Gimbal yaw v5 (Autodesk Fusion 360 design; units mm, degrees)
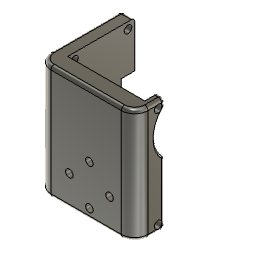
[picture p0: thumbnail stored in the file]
sketch "草图1" plane through (0, 0, 0) normal (1, 0, 0) x axis (0, 1, 0)
  line L1 (-10, 3.25) -> (-6, 3.25)
  line L2 (10, -1.75) -> (-10, -1.75)
  line L3 (10, 3.25) -> (6, 3.25)
  line L4 (-10, -17) -> (10, -17)
  line L5 (10, 17) -> (-10, 17)
  line L6 (10, 17) -> (-10, -17)
  line L7 (10, -6.75) -> (10, 3.25)
  line L8 (10, -17) -> (10, 17)
  line L9 (-10, 3.25) -> (-6, -6.75)
  line L10 (-6, 3.25) -> (-10, -6.75)
  line L11 (6, -6.75) -> (10, -6.75)
  line L12 (-10, -6.75) -> (-10, 3.25)
  line L13 (-6, 3.25) -> (-6, -6.75)
  line L14 (6, 3.25) -> (6, -6.75)
  line L15 (10, 0) -> (-10, 0)
  line L16 (-6, -6.75) -> (-10, -6.75)
  line L17 (0, -17) -> (0, 17)
  line L18 (-10, 17) -> (-10, -17)
  line L19 (-10, 17) -> (10, -17)
  circle C1 centre (0, 8) radius 1.3
  circle C2 centre (0, 8) radius 3
  circle C3 centre (8, -15) radius 1.125
  circle C4 centre (0, 8) radius 4
  circle C5 centre (-8, 15) radius 1.125
  circle C6 centre (8, 15) radius 1.125
  circle C7 centre (-8, -15) radius 1.125
  circle C8 centre (0, 8) radius 9
  point P26 (0, 0)
  point P21 (0, 0)
  point P8 (-8, -1.75)
  point P4 (-10, -6.75)
  point P19 (0, 17)
  point P20 (0, -17)
  point P10 (10, -6.75)
  point P5 (-6, -6.75)
  point P12 (6, -6.75)
  point P6 (-6, 3.25)
  point P11 (6, 3.25)
  point P7 (-10, 3.25)
  point P9 (10, 3.25)
  point P3 (10, -1.75)
  point P2 (-10, -1.75)
  point P13 (0, 8)
  point P15 (-10, 0)
  point P29 (10, 0)
  point P1 (0, 0)
  point P24 (-10, 17)
  point P25 (10, 17)
  point P22 (10, -17)
  point P14 (-8, 15)
  horizontal L4
  perpendicular L4 L18
  parallel L4 L5
  parallel L8 L18
  coincident P26 L19
  coincident P26 L6
  coincident P21 P26
  horizontal L16
  perpendicular L13 L16
  parallel L1 L16
  parallel L12 L13
  coincident P8 L10
  coincident P8 L9
  coincident P4 L18
  coincident P8 L2
  midpoint P19 L5
  midpoint P20 L4
  symmetric P4 P10 L17
  symmetric P5 P12 L17
  symmetric P6 P11 L17
  symmetric P7 P9 L17
  midpoint P3 L7
  midpoint P2 L12
  coincident P13 L17
  midpoint P15 L18
  midpoint P29 L8
  symmetric C5 C6 L17
  symmetric C5 C7 L15
  symmetric C3 C6 L15
  concentric C1 C2
  concentric C2 C4
  coincident P1 P26
  concentric C1 C8
  dimension "d1" distance P24 P25 = 20
  dimension "d2" distance P22 P25 = 34
  dimension "d3" distance P5 P6 = 10
  dimension "d4" distance P6 P7 = 4
  dimension "d5" diameter C1 = 2.6
  dimension "d6" distance P14 L17 = 8
  dimension "d7" distance P14 L15 = 15
  dimension "d8" diameter C5 = 2.25
  dimension "d9" distance P13 P14 = 7
  dimension "d10" diameter C2 = 6
  dimension "d11" diameter C4 = 8
  dimension "d12" distance L4 L11 = 10.25
  dimension "d81" diameter C8 = 18
sketch "草图2" plane through (0, 0, 0) normal (1, 0, 0) x axis (0, 1, 0)
extrude "拉伸1" new body sketch "草图1" profile of L1 L3 C3 L4 L5 L8 C5 C6 L11 C7 L13 L14 L16 L18 along normal blind 4
sketch "草图6" plane through (0, 0, 0) normal (-1, 0, 0) x axis (0, -1, 0)
  line L1 (-10, -6.75) -> (-6, -6.75)
  line L2 (-10, -17) -> (-10, -6.75)
  line L3 (10, -17) -> (-10, -17)
  line L4 (10, -6.75) -> (10, -17)
  line L5 (6, -6.75) -> (10, -6.75)
  line L6 (6, 3.25) -> (6, -6.75)
  line L7 (10, 3.25) -> (6, 3.25)
  line L8 (10, 17) -> (10, 3.25)
  line L9 (-10, 17) -> (10, 17)
  line L10 (-10, 3.25) -> (-10, 17)
  line L11 (-6, 3.25) -> (-10, 3.25)
  line L12 (-6, -6.75) -> (-6, 3.25)
  line L13 (15, 17) -> (10, 17)
  line L14 (15, -17) -> (15, 17)
  line L15 (10, -17) -> (15, -17)
  line L16 (10, 17) -> (10, -17)
  circle C1 centre (-8, 15) radius 1.125
  circle C2 centre (-8, -15) radius 1.125
  circle C3 centre (8, -15) radius 1.125
  circle C4 centre (8, 15) radius 1.125
  point P14 (10, 17)
  point P18 (10, 17)
  point P20 (15, -17)
  point P21 (10, -17)
  horizontal L13
  vertical L14
  horizontal L15
  vertical L16
  coincident P14 P18
  collinear L3 L15
  dimension "d46" distance P20 P21 = 5
extrude "拉伸6" add sketch "草图6" profile of L4 L8 L13 L14 L15 L16 against normal blind 27 (magnitude of "-23 mm - 4 mm")
sketch "草图7" plane through (0, -10, 0) normal (0, 1, 0) x axis (-1, 0, 0)
  line L1 (-4, -6.75) -> (-4, -17)
  line L2 (0, -6.75) -> (-4, -6.75)
  line L3 (0, 3.25) -> (0, -6.75)
  line L4 (-4, 3.25) -> (0, 3.25)
  line L5 (-4, 17) -> (-4, 3.25)
  line L6 (-27, 17) -> (-4, 17)
  line L7 (-27, -17) -> (-27, 17)
  line L8 (-4, -17) -> (-27, -17)
  line L9 (-4, 1) -> (-27, 1)
  line L10 (-4, 3.25) -> (-4, -6.75)
  line L11 (-15.5, -8) -> (-15.5, 1)
  circle C1 centre (-15.5, -8) radius 9
  circle C2 centre (-15.5, -2) radius 1.125
  circle C3 centre (-15.5, -2) radius 2.125
  circle C4 centre (-21.5, -8) radius 2.125
  circle C5 centre (-21.5, -8) radius 1.125
  circle C6 centre (-15.5, -14) radius 2.125
  circle C7 centre (-15.5, -14) radius 1.125
  circle C8 centre (-9.5, -8) radius 2.125
  circle C9 centre (-9.5, -8) radius 1.125
  point P10 (-27, 1)
  point P3 (-4, -6.75)
  point P12 (-4, -6.75)
  point P6 (-4, 3.25)
  point P13 (-4, 3.25)
  point P11 (-4, 1)
  point P14 (-15.5, 1)
  point P15 (-15.5, -8)
  point P16 (-15.5, -8)
  point P17 (-15.5, -2)
  coincident L7 P10
  perpendicular L7 L9
  coincident P3 P12
  coincident P6 P13
  coincident P11 L10
  midpoint L9 P14
  perpendicular L9 L11
  coincident P15 P16
  tangent L8 C1
  tangent L9 C1
  dimension "d49" distance L6 L9 = 16
  dimension "d50" distance P16 P17 = 6
  dimension "d51" diameter C2 = 2.25
  dimension "d52" = 1
  dimension "d54" C-Pattern1-Angle = 360
extrude "拉伸7" cut sketch "草图7" profile of C2 C5 C7 C9 against normal blind 5
extrude "拉伸8" cut sketch "草图7" profile of C2 C3 C4 C5 C6 C7 C8 C9 against normal blind 2
fillet "圆角9" radius 4
fillet "圆角10" radius 2
fillet "圆角11" radius 1
sketch "草图8" plane through (4, 0, 0) normal (1, 0, 0) x axis (0, 1, 0)
  line L1 (10, -6.75) -> (10, -16)
  line L2 (6, -6.75) -> (10, -6.75)
  line L3 (6, 3.25) -> (6, -6.75)
  line L4 (10, 3.25) -> (6, 3.25)
  line L5 (10, 16) -> (10, 3.25)
  line L6 (-10, 17) -> (9, 17)
  line L7 (-10, 3.25) -> (-10, 17)
  line L8 (-6, 3.25) -> (-10, 3.25)
  line L9 (-6, -6.75) -> (-6, 3.25)
  line L10 (-10, -6.75) -> (-6, -6.75)
  line L11 (-10, -17) -> (-10, -6.75)
  line L12 (9, -17) -> (-10, -17)
  line L13 (-6, -17) -> (-6, 17)
  line L14 (-10, -6.75) -> (-10, 3.25)
  arc A1 centre (9, -16) radius 1 clockwise from (10, -16) to (9, -17)
  arc A2 centre (9, 16) radius 1 clockwise from (9, 17) to (10, 16)
  circle C1 centre (8, 15) radius 1.125
  circle C2 centre (8, -15) radius 1.125
  circle C3 centre (-8, -15) radius 1.125
  circle C4 centre (-8, 15) radius 1.125
  point P22 (-6, 17)
  point P23 (-6, -17)
  point P13 (-10, 3.25)
  point P24 (-10, 3.25)
  point P16 (-10, -6.75)
  point P25 (-10, -6.75)
  coincident L6 P22
  coincident L12 P23
  perpendicular L12 L13
  coincident P13 P24
  coincident P16 P25
  dimension "d69" distance L11 L13 = 4
extrude "拉伸9" sketch "草图8" profile of L6 L7 L8 L9 L10 L11 L12 C3 C4 L13 L14 blind 2
extrude "拉伸10" add of existing geometry blind 2
fillet "圆角14" radius 4
fillet "圆角15" radius 1
fillet "圆角16" radius 1
extrude "拉伸11" sketch "草图1" profile of L1 L3 L13 L14 C8 to an object
fillet "圆角17" radius 0.5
